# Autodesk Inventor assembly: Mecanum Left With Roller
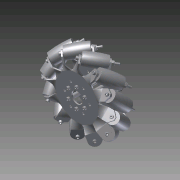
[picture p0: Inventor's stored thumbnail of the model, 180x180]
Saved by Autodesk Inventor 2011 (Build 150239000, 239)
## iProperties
Created: 2011-01
Part Number: Mecanum Left With Roller
Document SubType Name: Assembly
Designer: dfranz
Author: dfranz
Translation Standard: STEP AP203
FileName: //Amserv/amserver/AndyMark/Products/Wheel Mecanum/8 Mecanum Wheel/8 mecanum left with roller.stp
PreProcessor: Unknown
PostProcessor: Build: 239, Release: 2011 RTM - Date: Wed 02/17/2010
Sent Units: millimeter
Uncertainty: 0.001
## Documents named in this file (9)
- R:\CAD Archives\Wheels\Mecanum\Mecanum Left With Roller.iam
- \\storage\dfranz$\Inventor\#10 LockNut.ipt
- \\storage\dfranz$\Inventor\Middle Axle.ipt
- \\storage\dfranz$\Inventor\MBC Bushing MU04TH04.ipt
- \\storage\dfranz$\Inventor\washer.ipt
- \\storage\dfranz$\Inventor\SHCS 10-32x3_SHCS 10-32x3.ipt
- \\storage\dfranz$\Inventor\Mid Roller III.ipt
- \\storage\dfranz$\Inventor\8 Mecanum Plate Left.ipt
- \\storage\dfranz$\Inventor\Spacer5.ipt
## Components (116 placed, 8 different names)
1. #10 LockNut:1
2. #10 LockNut:2
3. #10 LockNut:3
4. #10 LockNut:4
5. #10 LockNut:5
6. #10 LockNut:6
7. #10 LockNut:7
8. #10 LockNut:8
9. #10 LockNut:9
10. #10 LockNut:10
11. #10 LockNut:11
12. #10 LockNut:12
13. #10 LockNut:13
14. #10 LockNut:14
15. #10 LockNut:15
16. #10 LockNut:16
17. #10 LockNut:17
18. #10 LockNut:18
19. Middle Axle:1
20. Middle Axle:2
21. Middle Axle:3
22. Middle Axle:4
23. Middle Axle:5
24. Middle Axle:6
25. Middle Axle:7
26. Middle Axle:8
27. Middle Axle:9
28. Middle Axle:10
29. Middle Axle:11
30. Middle Axle:12
31. MBC Bushing MU04TH04:1
32. MBC Bushing MU04TH04:2
33. MBC Bushing MU04TH04:3
34. MBC Bushing MU04TH04:4
35. MBC Bushing MU04TH04:5
36. MBC Bushing MU04TH04:6
37. MBC Bushing MU04TH04:7
38. MBC Bushing MU04TH04:8
39. MBC Bushing MU04TH04:9
40. MBC Bushing MU04TH04:10
41. MBC Bushing MU04TH04:11
42. MBC Bushing MU04TH04:12
43. MBC Bushing MU04TH04:13
44. MBC Bushing MU04TH04:14
45. MBC Bushing MU04TH04:15
46. MBC Bushing MU04TH04:16
47. MBC Bushing MU04TH04:17
48. MBC Bushing MU04TH04:18
49. MBC Bushing MU04TH04:19
50. MBC Bushing MU04TH04:20
51. MBC Bushing MU04TH04:21
52. MBC Bushing MU04TH04:22
53. MBC Bushing MU04TH04:23
54. MBC Bushing MU04TH04:24
55. washer:1
56. washer:2
57. washer:3
58. washer:4
59. washer:5
60. washer:6
61. washer:7
62. washer:8
63. washer:9
64. washer:10
65. washer:11
66. washer:12
67. washer:13
68. washer:14
69. washer:15
70. washer:16
71. washer:17
72. washer:18
73. washer:19
74. washer:20
75. washer:21
76. washer:22
77. washer:23
78. washer:24
79. SHCS 10-32x3_SHCS 10-32x3:1
80. SHCS 10-32x3_SHCS 10-32x3:2
81. SHCS 10-32x3_SHCS 10-32x3:3
82. SHCS 10-32x3_SHCS 10-32x3:4
83. SHCS 10-32x3_SHCS 10-32x3:5
84. SHCS 10-32x3_SHCS 10-32x3:6
85. SHCS 10-32x3_SHCS 10-32x3:7
86. SHCS 10-32x3_SHCS 10-32x3:8
87. SHCS 10-32x3_SHCS 10-32x3:9
88. SHCS 10-32x3_SHCS 10-32x3:10
89. SHCS 10-32x3_SHCS 10-32x3:11
90. SHCS 10-32x3_SHCS 10-32x3:12
91. SHCS 10-32x3_SHCS 10-32x3:13
92. SHCS 10-32x3_SHCS 10-32x3:14
93. SHCS 10-32x3_SHCS 10-32x3:15
94. SHCS 10-32x3_SHCS 10-32x3:16
95. SHCS 10-32x3_SHCS 10-32x3:17
96. SHCS 10-32x3_SHCS 10-32x3:18
97. Mid Roller III:1
98. Mid Roller III:2
99. Mid Roller III:3
100. Mid Roller III:4
101. Mid Roller III:5
102. Mid Roller III:6
103. Mid Roller III:7
104. Mid Roller III:8
105. Mid Roller III:9
106. Mid Roller III:10
107. Mid Roller III:11
108. Mid Roller III:12
109. 8 Mecanum Plate Left:1
110. 8 Mecanum Plate Left:2
111. Spacer5:1
112. Spacer5:2
113. Spacer5:3
114. Spacer5:4
115. Spacer5:5
116. Spacer5:6
